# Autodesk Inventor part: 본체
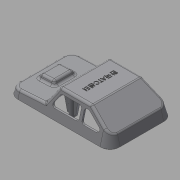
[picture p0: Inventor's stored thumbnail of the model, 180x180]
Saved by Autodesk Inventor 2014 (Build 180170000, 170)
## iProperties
Created: 2015-05
Part Number: 본체
Material: Generic
Document SubType Name: Modeling
Designer: Administrator
Density: 1 g/cm^3
Appearance: Default
Author: Administrator
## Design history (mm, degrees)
sketch "스케치1"
  geometry: L1 (-49, 38)-(49, 38); L2 (61, 26)-(61, -26); L3 (49, -38)-(-49, -38); L4 (-61, -26)-(-61, 26); L5 (-61, 38)-(61, -38); L6 (61, 38)-(-61, -38); A1 r 12 centre (-49, 26) between (-49, 38) and (-61, 26); A2 r 12 centre (49, 26) between (61, 26) and (49, 38); A3 r 12 centre (49, -26) between (49, -38) and (61, -26); A4 r 12 centre (-49, -26) between (-61, -26) and (-49, -38); 1 further point
  constraints: 12 end point, 8 point on circle, 8 point on line, 8 tangent, 4 centre point, 3 equal radius, 2 midpoint, 2 parallel, 1 horizontal, 1 perpendicular
  dimensions: "d0" = 122 distance of L5.end L6.end; "d1" = 76 distance of L6.start L5.end; "d2" = 12 radius of A1
extrude "돌출1" new body sketch "스케치1" distance "d3" = 30; taper "d4" = -15 deg
sketch "스케치2"
  geometry: L1 (-61, 30)-(-61, 10); L2 (-61, 10)-(-31, 30); L3 (-31, 30)-(-61, 30); L4 (-61, 0)-(-52.962, 30) reference; L5 (-49, 30)-(49, 30) reference; 1 further point
  constraints: 6 end point, 1 collinear, 1 perpendicular, 1 vertical, 1 vertical alignment
  dimensions: "d5" = 20 distance of L1.start L1.end; "d6" = 30 distance of L2.end L1.start
extrude "돌출2" cut sketch "스케치2" stored distance "d7" = 30; taper "d8" = 0 deg
sketch "스케치3"
  geometry: L1 (6.628, 30)-(61, 30); L2 (61, 30)-(61, 8); L3 (19, 10.201)-(6.628, 30); L4 (-31, 30)-(49, 30) reference; L5 (61, 0)-(52.962, 30) reference; L6 (49, 0)-(61, 0) reference; L7 (19, 10.201)-(61, 8); 1 further point
  constraints: 8 end point, 1 collinear, 1 horizontal, 1 perpendicular, 1 vertical alignment
  dimensions: "d11" = 3 deg angle of L6 L7; "d12" = 8 distance from line of L6 L2.end; "d13" = 125 deg angle of L7 L3; "d14" = 42 horizontal distance of L2.end L3.start
extrude "돌출3" cut sketch "스케치3" stored distance "d15" = 30; taper "d16" = 0 deg
sketch "스케치4"
  geometry: L1 (-31.476, 48.267)-(-11.476, 48.267); L2 (-11.476, 48.267)-(-11.476, 22.267); L3 (-11.476, 22.267)-(-31.476, 22.267); L4 (-31.476, 22.267)-(-31.476, 48.267); L5 (-42.476, 9.267)-(-42.476, 61.267) reference; 3 further points
  constraints: 8 end point, 2 midpoint, 2 parallel, 1 horizontal, 1 horizontal alignment, 1 perpendicular
  dimensions: "d17" = 11 distance between parallel lines of L5 L4; "d18" = 20 distance of L2.end L3.end; "d19" = 26 distance of L1.end L2.end
extrude "돌출4" join sketch "스케치4" distance "d20" = 5; taper "d21" = -20 deg
fillet "모깎기1" dims "d22" = 3
fillet "모깎기2" dims "d23" = 3
fillet "모깎기3" dims "d24" = 3
fillet "모깎기4" dims "d25" = 3
feature "쉘1" dims "d26" = 2
node "작업 평면1"
sketch "스케치6"
  geometry: A1 r 4 centre (-21, 0) between (-17, 0) and (-25, 0); A2 r 4 centre (-10, 0) between (-6, 0) and (-14, 0); A3 r 4 centre (10, 0) between (14, 0) and (6, 0); A4 r 4 centre (21, 0) between (25, 0) and (17, 0); 3 further points
  constraints: 8 point on circle, 4 centre point, 4 horizontal alignment, 9 other
  dimensions: "d28" = 8 diameter of A1; "d29" = 8 diameter of A2; "d30" = 8 diameter of A3; "d31" = 8 diameter of A4; "d32" = 10 distance of point (0, 0) A2.centre; "d33" = 20 distance of A3.centre A2.centre; "d34" = 11 distance of A2.centre A1.centre; "d35" = 11 distance of A4.centre A3.centre
extrude "돌출5" join sketch "스케치6" stored distance "d36" = 5; taper "d37" = 0 deg
chamfer "모따기1" distance "d38" = 1; stored, may be unused: second distance "d39" = 2, angle "d40" = 45 deg
sketch "스케치7"
  geometry: L1 (58.929, 26)-(58.929, -26) reference; L2 (49, -35.929)-(-49, -35.929) reference; L3 (-58.929, -26)-(-58.929, 26) reference; L4 (-49, 35.929)-(49, 35.929) reference; L5 (49, 36.929)-(-49, 36.929); L6 (-59.929, 26)-(-59.929, -26); L7 (-49, -36.929)-(49, -36.929); L8 (59.929, -26)-(59.929, 26); A1 r 9.929 centre (49, -26) between (49, -35.929) and (58.929, -26) reference; A2 r 9.929 centre (-49, -26) between (-58.929, -26) and (-49, -35.929) reference; A3 r 9.929 centre (-49, 26) between (-49, 35.929) and (-58.929, 26) reference; A4 r 9.929 centre (49, 26) between (58.929, 26) and (49, 35.929) reference; A5 r 10.929 centre (-49, 26) between (-49, 36.929) and (-59.929, 26); A6 r 10.929 centre (-49, -26) between (-59.929, -26) and (-49, -36.929); A7 r 10.929 centre (49, -26) between (49, -36.929) and (59.929, -26); A8 r 10.929 centre (49, 26) between (59.929, 26) and (49, 36.929); 1 further point
  constraints: 8 end point, 8 point on circle, 4 centre point, 7 other
  dimensions: "d41" = 1 distance between parallel lines of L4 L5
extrude "돌출6" join sketch "스케치7" distance "d42" = 1; taper "d43" = 0 deg
sketch "스케치8"
  geometry: L1 (-50.664, 16.891)-(-31.756, 29.496) reference; L2 (-30.092, 30)-(4.965, 30) reference; L3 (7.51, 28.59)-(18.172, 11.526) reference; L4 (4.738, 23.59)-(10.362, 14.59); L5 (7.818, 10)-(-17.77, 10); L6 (-20.77, 13)-(-20.77, 22); L7 (-17.77, 25)-(2.194, 25); L8 (-43.742, 15.496)-(-30.242, 24.496); L9 (-42.078, 10)-(-26.986, 10); L10 (-23.986, 13)-(-23.986, 22); L11 (-26.986, 25)-(-28.578, 25); A1 r 3 centre (-17.77, 22) between (-17.77, 25) and (-20.77, 22); A2 r 3 centre (2.194, 22) between (4.738, 23.59) and (2.194, 25); A3 r 3 centre (7.818, 13) between (7.818, 10) and (10.362, 14.59); A4 r 3 centre (-17.77, 13) between (-20.77, 13) and (-17.77, 10); A5 r 3 centre (-26.986, 22) between (-23.986, 22) and (-26.986, 25); A6 r 3 centre (-28.578, 22) between (-28.578, 25) and (-30.242, 24.496); A7 r 3 centre (-26.986, 13) between (-26.986, 10) and (-23.986, 13); A8 r 3 centre (-42.078, 13) between (-43.742, 15.496) and (-42.078, 10); 5 further points
  constraints: 16 end point, 16 point on circle, 16 tangent, 8 centre point, 8 point on line, 6 equal radius, 6 parallel, 2 perpendicular
  dimensions: "d44" = 5 distance between parallel lines of L3 L4; "d45" = 5 distance between parallel lines of L2 L7; "d46" = 15 distance between parallel lines of L5 L7; "d47" = 34 distance of point (13.23, 10) point (-20.77, 10); "d48" = 3 radius of A1; "d49" = 5 distance between parallel lines of L2 L11; "d50" = 5 distance between parallel lines of L1 L8; "d51" = 15 distance between parallel lines of L11 L9; "d52" = 28 distance of point (-51.986, 10) point (-23.986, 10); "d53" = 3 radius of A5
extrude "돌출7" cut sketch "스케치8" stored distance "d54" = 1; taper "d55" = 0 deg
sketch "스케치9"
  geometry: C1 r 3 at (-40, 0); C2 r 3 at (0, -22); C3 r 3 at (0, 22); C4 r 3 at (40, 0); 1 further point
  constraints: 4 centre point, 2 horizontal alignment, 2 vertical alignment
  dimensions: "d56" = 6 diameter of C1; "d57" = 6 diameter of C2; "d58" = 6 diameter of C3; "d59" = 6 diameter of C4; "d60" = 40 distance of C4.centre point (0, 0); "d61" = 22 distance of point (0, 0) C2.centre; "d62" = 44 distance of C3.centre C2.centre; "d63" = 40 distance of C1.centre point (0, 0)
extrude "돌출8" join sketch "스케치9" stored distance "d64" = 1; taper "d65" = 2 deg
node "작업 평면2"
sketch "스케치10"
  geometry: L1 (-45, 1)-(-35, 1); L2 (-35, 1)-(-35, -1); L3 (-35, -1)-(-45, -1); L4 (-45, -1)-(-45, 1); L5 (-45, 1)-(-35, -1); L6 (-35, 1)-(-45, -1); L7 (-5, 23)-(5, 23); L8 (5, 23)-(5, 21); L9 (5, 21)-(-5, 21); L10 (-5, 21)-(-5, 23); L11 (-5, 23)-(5, 21); L12 (5, 23)-(-5, 21); L13 (-5, -21)-(5, -21); L14 (5, -21)-(5, -23); L15 (5, -23)-(-5, -23); L16 (-5, -23)-(-5, -21); L17 (-5, -21)-(5, -23); L18 (5, -21)-(-5, -23); L19 (35, 1)-(45, 1); L20 (45, 1)-(45, -1); L21 (45, -1)-(35, -1); L22 (35, -1)-(35, 1); L23 (35, 1)-(45, -1); L24 (45, 1)-(35, -1); C1 r 3 at (-40, 0) reference; C2 r 3 at (0, 22) reference; C3 r 3 at (40, 0) reference; C4 r 3 at (0, -22) reference; 1 further point
  constraints: 48 end point, 8 midpoint, 8 parallel, 4 horizontal, 4 perpendicular
  dimensions: "d67" = 10 distance of L2.end L3.end; "d68" = 2 distance of L1.end L2.end; "d69" = 10 distance of L8.end L9.end; "d70" = 2 distance of L7.end L8.end; "d71" = 10 distance of L14.end L15.end; "d72" = 2 distance of L13.end L14.end; "d73" = 10 distance of L20.end L21.end; "d74" = 2 distance of L19.end L20.end
extrude "돌출9" join sketch "스케치10" stored distance "d75" = 1; taper "d76" = 2.5 deg
sketch "스케치11"
  geometry: L1 (2.098, 0)-(3.233, -26.025) reference; L2 (27.189, -25.764)-(-7.868, -25.764) reference; L3 (2.098, 0)-(6.64, -25.764); L4 (6.64, -25.764)-(3.221, -25.764); L5 (2.098, 0)-(3.221, -25.764); 1 further point
  constraints: 6 end point, 3 point on line, 1 collinear
  dimensions: "d79" = 80 deg angle of L2 L3
extrude "돌출10" join sketch "스케치11" stored distance "d80" = 10; taper "d81" = 0 deg
sketch "스케치14"
  geometry: L1 (2.098, 0)-(2.551, -10.4) reference; L2 (-2.896, -10.052)-(-2.902, 2.042); L3 (2.098, 0)-(4.014, -10.835); L4 (4.014, -10.835)-(2.551, -10.4); 16 further points; 9 other entities
  constraints: 6 end point, 9 other
  dimensions: "d90" = 10 deg angle of L3 L2; "d91" = 1.46262 horizontal distance of L3.end L1.end
extrude "돌출13" join sketch "스케치14" stored distance "d92" = 10; taper "d93" = 0 deg
sketch "스케치15"
  geometry: L1 (0, 0)-(-0.429, -9.83) reference; L2 (5, 2.042)-(5.006, -10.052); L3 (0, 0)-(-1.716, -9.762); L4 (-0.429, -9.83)-(-1.716, -9.762); L5 (-0.429, -9.83)-(0, 0); 16 further points; 9 other entities
  constraints: 8 end point, 10 other
  dimensions: "d94" = 10 deg angle of L3 L2
extrude "돌출14" join sketch "스케치15" stored distance "d95" = 10; taper "d96" = 0 deg
sketch "스케치16"
  geometry: L1 (2.098, 0)-(2.788, -15.818) reference; L2 (-8.934, -23.462)-(-6.199, -21.645) reference; L3 (-7.902, 0.087)-(-8.934, -23.462) reference; L4 (-7.902, 0.087)-(-5.805, 0.087) reference; L5 (2.098, 0)-(4.606, -14.605); L6 (-7.902, 0.087)-(-12.642, -26.112); L7 (-2.902, 0.044)-(-2.99, -19.592); L8 (-6.199, -21.815)-(-12.642, -26.112); L9 (2.788, -15.818)-(4.606, -14.605); L10 (-8.941, -23.644)-(-7.902, 0.087); L11 (2.788, -15.818)-(2.098, 0); 16 further points; 10 other entities
  constraints: 14 end point, 2 collinear, 1 parallel, 1 point on line, 11 other
  dimensions: "d97" = 10 deg angle of L6 L7; "d98" = 20 deg angle of L6 L5
extrude "돌출15" join sketch "스케치16" stored distance "d99" = 10; taper "d100" = 0 deg
sketch "스케치17"
  geometry: L1 (0, 0)-(-1.095, -25.103) reference; L2 (-0.813, -25.554)-(-1.095, -25.103) reference; L3 (5, -25.932)-(5, 0.044); L4 (0, 0)-(-3.693, -20.942); L5 (-1.095, -25.103)-(-3.693, -20.942); 16 further points; 9 other entities
  constraints: 6 end point, 1 collinear, 1 vertical, 9 other
  dimensions: "d101" = 10 deg angle of L3 L4
extrude "돌출16" join sketch "스케치17" stored distance "d102" = 10; taper "d103" = 0 deg
sketch "스케치18"
  geometry: L1 (-1.095, 25.103)-(-0.813, 25.554) reference; L2 (0, 0)-(-1.095, 25.103) reference; L3 (5, -0.044)-(5, 25.932); L4 (0, 0)-(-3.693, 20.942); L5 (-1.095, 25.103)-(-3.693, 20.942); 16 further points; 9 other entities
  constraints: 6 end point, 1 collinear, 1 vertical, 9 other
  dimensions: "d104" = 10 deg angle of L3 L4
extrude "돌출17" join sketch "스케치18" stored distance "d105" = 10; taper "d106" = 0 deg
sketch "스케치19"
  geometry: C1 r 3 at (0, 0) reference; C2 r 3 at (-40, -22) reference; C3 r 3 at (0, -44) reference; C4 r 3 at (40, -22) reference; 5 further points
  constraints: 4 coincident
hole "구멍1" sketch "스케치19" at (-40, -22), (0, 0), (40, -22), (0, -44) diameter "d107" = 3.242; stored, may be unused: countersink angle "d111" = 90 deg, drill point angle "d113" = 118 deg; dims "d108" = 9, "d109" = 4, "d110" = 2, "d112" = 11
sketch "스케치20"
  geometry: L1 (61, 26)-(61, -26) reference; 2 further points
  constraints: 1 horizontal alignment, 1 other
  dimensions: "d114" = 50 distance from line of L1 point (11, 0)
feature "엠보싱1" sketch "스케치20" dims "d0" = 122, "d1" = 76, "d2" = 12, "d115" = 0.5, "d116" = 0
node "솔리드1"
mirror "대칭1"
node "투영된 루프1"
node "투영된 루프2"
node "투영된 루프3"
node "투영된 루프4"
node "투영된 루프5"
node "투영된 루프6"
node "투영된 루프7"
node "투영된 루프8"
node "투영된 루프9"
node "투영된 루프10"
node "투영된 루프11"
node "투영된 루프12"
node "투영된 루프13"
other parameters: "d27" = -63, "d66" = 2
